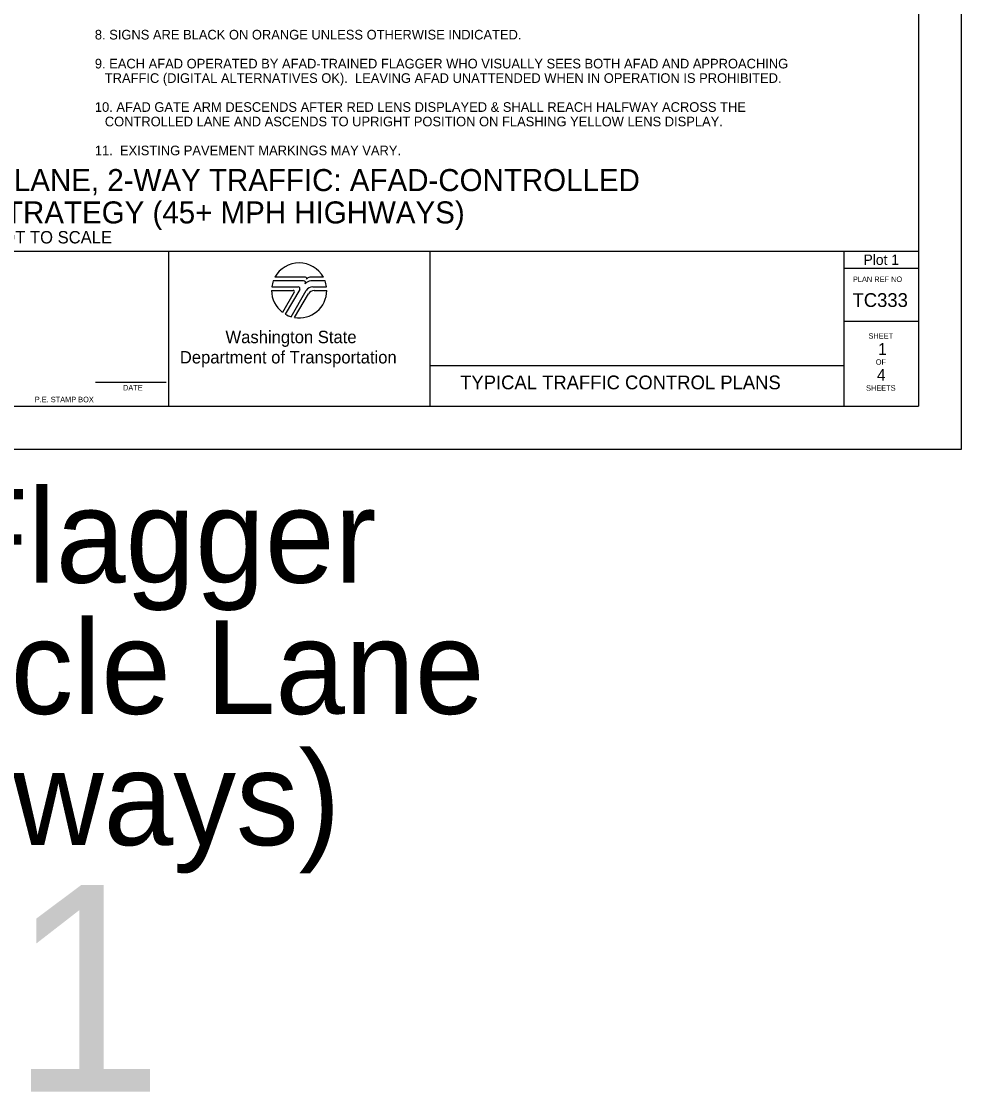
# Model space of a CAD drawing. Extents: x 99999.1 to 100095.7, y 99995 to 100010.7.
# Drawn here: x 100009.24 to 100016.06, y 99995.01 to 100002.79 of the extents above; entities that cross this region are included whole.
import ezdxf

# ---------------------------------------------------------------- set-up
doc = ezdxf.new("R2010")
doc.units = 0
for name, color, linetype in [('SH_DE_DetailHeading1Text', 7, 'Continuous'), ('SH_GI_GeneralNotesBodyText', 7, 'Continuous'), ('SH_GI_PlotLimits', 7, 'Continuous'), ('SH_GI_SheetBorder', 7, 'Continuous'), ('SH_GI_SheetLocationText', 7, 'Continuous'), ('SH_GI_SheetTextInCells', 7, 'Continuous'), ('SH_GI_TitleBlockText', 7, 'Continuous'), ('SH_GI_WSDOTLogo', 7, 'Continuous')]:
    doc.layers.add(name, color=color, linetype=linetype)

msp = doc.modelspace()

# ---------------------------------------------------------------- linework, layer by layer
at = {"layer": 'SH_GI_PlotLimits'}
msp.add_lwpolyline([(99999.0625, 99999.6875), (100016.0625, 99999.6875), (100016.0625, 100010.6875), (99999.0625, 100010.6875)], close=True, dxfattribs=at)
at = {"layer": 'SH_GI_SheetBorder'}
for p, q in [((100015.75, 100010.375), (100015.75, 100000)), ((100000, 100001.1259), (100015.75, 100001.1259)), ((100010.3089, 100001.1259), (100010.3089, 100000)), ((100012.2055, 100001.1259), (100012.2055, 100000)), ((100015.2079, 100001.1259), (100015.2079, 100000)), ((100015.2079, 100001.0008), (100015.75, 100001.0008)), ((100015.2079, 100000.6176), (100015.75, 100000.6176)), ((100012.2055, 100000.2955), (100015.2079, 100000.2955)), ((100009.7797, 100000.1733), (100010.2914, 100000.1733)), ((100000, 100000), (100015.75, 100000))]:
    msp.add_line(p, q, dxfattribs=at)
at = {"layer": 'SH_GI_WSDOTLogo'}
for p, q in [((100011.2894, 100000.9094), (100011.0697, 100000.9094)), ((100011.303, 100000.9354), (100011.0815, 100000.9354)), ((100011.433, 100000.9354), (100011.3351, 100000.9354)), ((100011.343, 100000.9094), (100011.3429, 100000.9094)), ((100011.4448, 100000.9094), (100011.343, 100000.9094)), ((100011.0572, 100000.84), (100011.2148, 100000.84)), ((100011.059, 100000.8661), (100011.2496, 100000.8661)), ((100011.222, 100000.8277), (100011.1364, 100000.6807)), ((100011.261, 100000.8464), (100011.1567, 100000.6672)), ((100011.1989, 100000.6487), (100011.3089, 100000.839)), ((100011.3558, 100000.8661), (100011.4555, 100000.8661)), ((100011.3655, 100000.8394), (100011.4572, 100000.8394)), ((100011.2244, 100000.6428), (100011.3242, 100000.8156))]:
    msp.add_line(p, q, dxfattribs=at)
for centre, radius, start, end in [((100011.2572, 100000.84), 0.2, 28.47865, 151.53204), ((100011.2572, 100000.84), 0.2, 159.69598, 172.50569), ((100011.2894, 100000.8946), 0.0148, 327.8418, 89.99855), ((100011.3429, 100000.861), 0.0484, 89.99529, 147.82376), ((100011.303, 100000.9263), 0.00903, 329.87418, 90.00328), ((100011.3352, 100000.9066), 0.0287, 90.00721, 148.16763), ((100011.2572, 100000.84), 0.2, 7.49431, 20.29406), ((100011.2572, 100000.84), 0.2, 179.99864, 232.84327), ((100011.2149, 100000.8318), 0.0082, 329.74356, 90), ((100011.2572, 100000.84), 0.2, 260.54554, 359.80857), ((100011.2497, 100000.853), 0.0131, 329.76834, 90), ((100011.3558, 100000.8119), 0.0542, 90, 149.99738), ((100011.3654, 100000.7918), 0.0476, 90, 150.05432), ((100011.2572, 100000.84), 0.2, 239.79292, 253.0448)]:
    msp.add_arc(centre, radius, start, end, dxfattribs=at)

# ---------------------------------------------------------------- texts
at = {"layer": 'SH_DE_DetailHeading1Text'}
for s, height, p in [('PILOT CAR OPERATION FOR ALTERNATING 1-LANE, 2-WAY TRAFFIC: AFAD-CONTROLLED', 0.16, (100004.4207, 100001.5606)), ('SHARED BIKE-VEHICLE LANE STRATEGY (45+ MPH HIGHWAYS)', 0.16, (100005.8775, 100001.3259)), ('NOT TO SCALE', 0.09, (100009.0168, 100001.1809))]:
    msp.add_text(s, height=height, rotation=360, dxfattribs=at).set_placement(p)
at = {"layer": 'SH_GI_GeneralNotesBodyText'}
for s, p in [('8. SIGNS ARE BLACK ON ORANGE UNLESS OTHERWISE INDICATED.', (100009.7751, 100002.6606)), ('9. EACH AFAD OPERATED BY AFAD-TRAINED FLAGGER WHO VISUALLY SEES BOTH AFAD AND APPROACHING ', (100009.7751, 100002.4506)), ('TRAFFIC (DIGITAL ALTERNATIVES OK).  LEAVING AFAD UNATTENDED WHEN IN OPERATION IS PROHIBITED.', (100009.8473, 100002.3456)), ('10. AFAD GATE ARM DESCENDS AFTER RED LENS DISPLAYED & SHALL REACH HALFWAY ACROSS THE ', (100009.7751, 100002.1356)), ('CONTROLLED LANE AND ASCENDS TO UPRIGHT POSITION ON FLASHING YELLOW LENS DISPLAY.', (100009.8473, 100002.0306)), ('11.  EXISTING PAVEMENT MARKINGS MAY VARY.', (100009.7751, 100001.8206))]:
    msp.add_text(s, height=0.07, rotation=360, dxfattribs=at).set_placement(p)
at = {"layer": 'SH_GI_SheetBorder'}
msp.add_text('PLAN REF NO', height=0.040032, dxfattribs=at).set_placement((100015.2747, 100000.9008))
at = {"layer": 'SH_GI_SheetLocationText'}
for s, height, p in [('Plot 1', 0.075, (100015.3518, 100001.025)), ('Pilot Car Op: Flagger', 0.68, (100003.2766, 99998.7191)), ('Shared Bike-Vehicle Lane', 0.68, (100002.0877, 99997.7671)), ('(45+ mph Highways)', 0.68, (100003.1924, 99996.8151)), ('Plot 1', 1.5, (100005.1448, 99995.0267))]:
    msp.add_text(s, height=height, dxfattribs=at).set_placement(p)
at = {"layer": 'SH_GI_SheetTextInCells'}
for s, height, p in [('Washington State', 0.090072, (100010.7229, 100000.4571)), ('SHEET', 0.04003, (100015.3877, 100000.4896)), ('Department of Transportation', 0.090072, (100010.3916, 100000.3101)), ('OF', 0.04003, (100015.4406, 100000.3008)), ('DATE', 0.04003, (100009.9794, 100000.1141)), ('SHEETS', 0.04003, (100015.3698, 100000.112)), ('P.E. STAMP BOX', 0.040032, (100009.339, 100000.0286))]:
    msp.add_text(s, height=height, dxfattribs=at).set_placement(p)
at = {"layer": 'SH_GI_TitleBlockText'}
for s, height, p in [('TC333', 0.1, (100015.2718, 100000.72)), ('1', 0.085, (100015.4566, 100000.3723)), ('TYPICAL TRAFFIC CONTROL PLANS', 0.1, (100012.4251, 100000.1224)), ('4', 0.085, (100015.4485, 100000.1843))]:
    msp.add_text(s, height=height, dxfattribs=at).set_placement(p)

doc.saveas('drawing.dxf')
